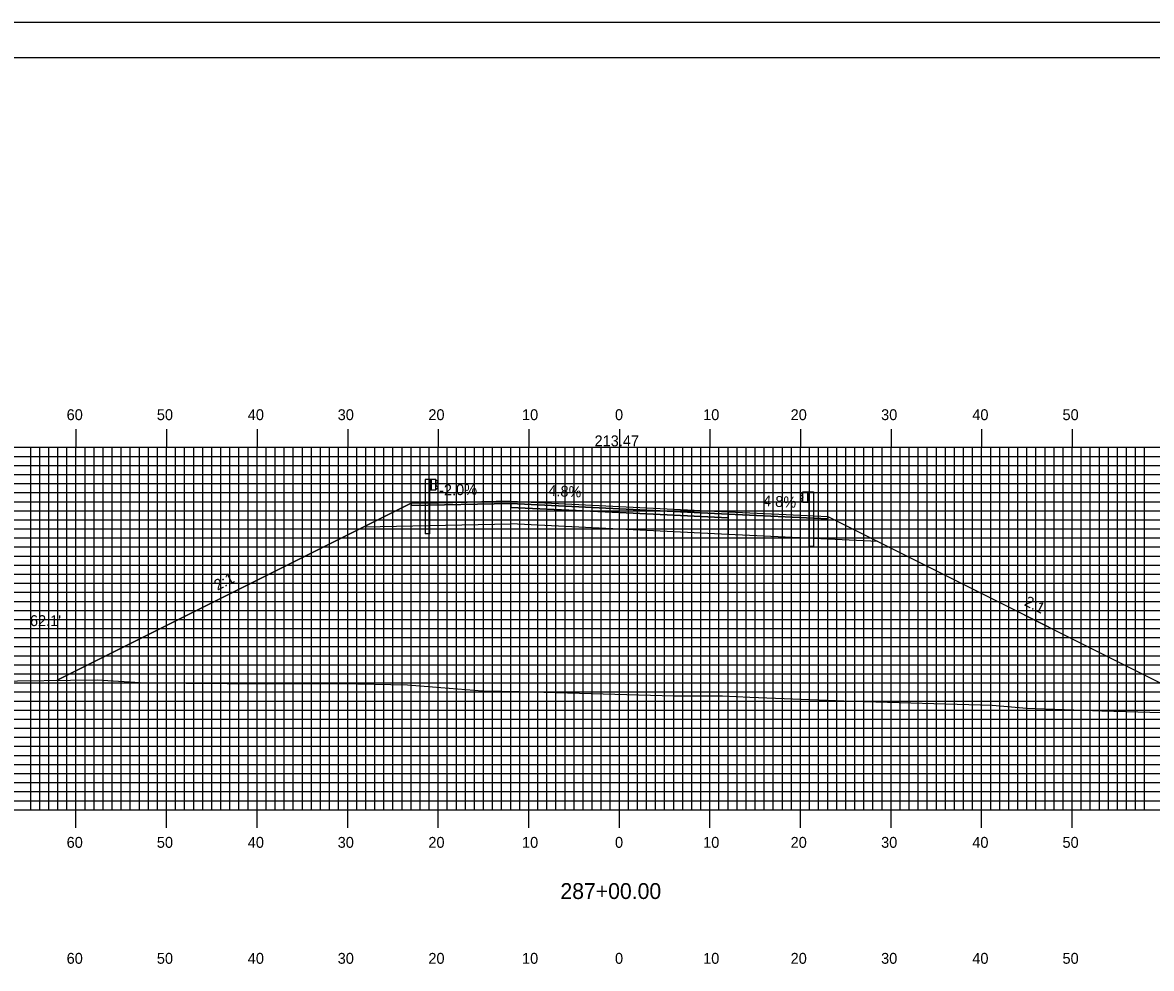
# Model space of a CAD drawing. Extents: x 1812554 to 1812897, y 442591 to 442811.
# Drawn here: x 1812654 to 1812778.7, y 442706.2 to 442810.5 of the extents above; entities that cross this region are included whole.
import ezdxf

# ---------------------------------------------------------------- set-up
doc = ezdxf.new("R2010")
doc.units = 0
for name, color, linetype in [('ANNOTATION', 7, 'Continuous'), ('BORDER', 7, 'Continuous'), ('D_Guardrail_Beam_Lt', 7, 'Continuous'), ('D_Guardrail_Beam_Rt', 7, 'Continuous'), ('D_Roadway_Centerline', 7, 'Continuous'), ('D_Roadway_Centerline_Text', 7, 'Continuous'), ('D_Roadway_Edge_Shoulder', 7, 'Continuous'), ('D_Roadway_Edge_TW', 7, 'Continuous'), ('D_Roadway_Pavement', 7, 'Continuous'), ('D_Roadway_SlopeLines', 7, 'Continuous'), ('D_Roadway_SubGrade', 7, 'Continuous'), ('D_Text_Standard', 7, 'Continuous'), ('H_V ANNOTATION', 7, 'Continuous'), ('MAJOR', 7, 'Continuous'), ('MINOR', 7, 'Continuous'), ('PLOT BOUNDARY', 7, 'Continuous'), ('S_Roadway_Centerline', 7, 'Continuous')]:
    doc.layers.add(name, color=color, linetype=linetype)

msp = doc.modelspace()

# ---------------------------------------------------------------- linework, layer by layer
at = {"layer": 'BORDER'}
msp.add_lwpolyline([(1812570.34, 442596.67), (1812890.34, 442596.67), (1812890.34, 442806.67), (1812570.34, 442806.67)], close=True, dxfattribs=at)
at = {"layer": 'D_Guardrail_Beam_Lt'}
for p, q in [((1812698.51, 442760.13), (1812698.51, 442754.13)), ((1812698.98, 442760.13), (1812698.51, 442760.13)), ((1812699.67, 442760.13), (1812698.98, 442760.13)), ((1812698.98, 442760.13), (1812698.98, 442758.96)), ((1812699.05, 442760.13), (1812699.05, 442758.96)), ((1812699.15, 442760.13), (1812699.15, 442758.96)), ((1812699.67, 442758.96), (1812699.67, 442760.13)), ((1812699.67, 442760.05), (1812699.75, 442760.03)), ((1812699.68, 442759.58), (1812699.68, 442759.51)), ((1812699.9, 442759.78), (1812699.71, 442759.65)), ((1812699.71, 442759.45), (1812699.9, 442759.31)), ((1812699.76, 442760.03), (1812699.9, 442759.93)), ((1812699.9, 442759.17), (1812699.76, 442759.07)), ((1812698.98, 442758.96), (1812699.67, 442758.96)), ((1812699, 442754.13), (1812699, 442758.96)), ((1812699.75, 442759.06), (1812699.67, 442759.05)), ((1812699, 442754.13), (1812698.51, 442754.13))]:
    msp.add_line(p, q, dxfattribs=at)
for centre, major_axis, start_param, end_param in [((1812699.75, 442759.58), (-0.0789, 0), 5.323254, 6.283185), ((1812699.75, 442759.51), (-0.0789, 0), 6.283185, 7.243116), ((1812699.74, 442759.99), (0.0417, 0), 0.959931, 1.376053), ((1812699.85, 442759.85), (0.0877, 0), 5.323254, 7.243116), ((1812699.85, 442759.24), (0.0877, 0), 5.323254, 7.243116), ((1812699.74, 442759.1), (0.0417, 0), 4.907132, 5.323254)]:
    msp.add_ellipse(centre, major_axis=major_axis, ratio=0.995501, start_param=start_param, end_param=end_param, dxfattribs=at)
at = {"layer": 'D_Guardrail_Beam_Rt'}
for p, q in [((1812740.12, 442758.65), (1812739.98, 442758.55)), ((1812739.98, 442758.41), (1812740.17, 442758.27)), ((1812740.17, 442758.07), (1812739.98, 442757.94)), ((1812740.21, 442758.67), (1812740.14, 442758.66)), ((1812740.21, 442758.75), (1812740.9, 442758.75)), ((1812740.21, 442757.59), (1812740.21, 442758.75)), ((1812740.21, 442758.21), (1812740.21, 442758.14)), ((1812740.73, 442758.75), (1812740.73, 442757.59)), ((1812740.84, 442758.75), (1812740.84, 442757.59)), ((1812740.9, 442758.75), (1812741.37, 442758.75)), ((1812740.9, 442758.75), (1812740.9, 442757.59)), ((1812741.37, 442758.75), (1812741.37, 442752.75)), ((1812739.98, 442757.79), (1812740.12, 442757.69)), ((1812740.14, 442757.69), (1812740.21, 442757.67)), ((1812740.9, 442757.59), (1812740.21, 442757.59)), ((1812740.88, 442752.75), (1812740.88, 442757.59)), ((1812740.88, 442752.75), (1812741.37, 442752.75))]:
    msp.add_line(p, q, dxfattribs=at)
for centre, major_axis, start_param, end_param in [((1812740.03, 442758.48), (-0.0877, 0), 5.323254, 7.243116), ((1812740.03, 442757.86), (-0.0877, 0), 5.323254, 7.243116), ((1812740.15, 442758.62), (-0.0417, 0), 4.907132, 5.323254), ((1812740.13, 442758.21), (0.0789, 0), 0, 0.959931), ((1812740.13, 442758.14), (0.0789, 0), 5.323254, 6.283185), ((1812740.15, 442757.73), (-0.0417, 0), 0.959931, 1.376053)]:
    msp.add_ellipse(centre, major_axis=major_axis, ratio=0.995501, start_param=start_param, end_param=end_param, dxfattribs=at)
at = {"layer": 'D_Roadway_Centerline'}
msp.add_lwpolyline([(1812657.88, 442737.96), (1812691.73, 442754.88), (1812696.94, 442757.49), (1812699.94, 442757.55), (1812707.94, 442757.71), (1812719.94, 442757.13), (1812731.94, 442756.55), (1812739.94, 442756.17), (1812742.94, 442756.03), (1812748.47, 442753.26), (1812786.29, 442734.35)], dxfattribs=at)
at = {"layer": 'D_Roadway_Edge_Shoulder'}
for points in [[(1812707.94, 442757.71), (1812699.94, 442757.55), (1812699.94, 442757.55), (1812696.94, 442757.49), (1812696.94, 442757.24), (1812707.94, 442757.46)], [(1812731.94, 442756.55), (1812739.94, 442756.17), (1812739.94, 442756.17), (1812742.94, 442756.03), (1812742.94, 442755.78), (1812731.94, 442756.3)]]:
    msp.add_lwpolyline(points, close=True, dxfattribs=at)
at = {"layer": 'D_Roadway_Edge_TW'}
msp.add_lwpolyline([(1812707.94, 442757.46), (1812707.94, 442757.71), (1812719.94, 442757.13), (1812731.94, 442756.55), (1812731.94, 442756.3), (1812719.94, 442756.88)], close=True, dxfattribs=at)
at = {"layer": 'D_Roadway_Pavement'}
msp.add_lwpolyline([(1812707.94, 442757.04), (1812707.94, 442757.46), (1812719.94, 442756.88), (1812731.94, 442756.3), (1812731.94, 442755.89), (1812719.94, 442756.46)], close=True, dxfattribs=at)
for points in [[(1812707.94, 442757.46), (1812707.94, 442757.04)], [(1812731.94, 442756.3), (1812731.94, 442755.89)]]:
    msp.add_lwpolyline(points, dxfattribs=at)
at = {"layer": 'D_Roadway_SlopeLines'}
for points in [[(1812696.94, 442757.49), (1812657.88, 442737.96)], [(1812742.94, 442756.03), (1812786.29, 442734.35)]]:
    msp.add_lwpolyline(points, dxfattribs=at)
at = {"layer": 'D_Roadway_SubGrade'}
for points in [[(1812707.94, 442757.04), (1812707.94, 442757.46), (1812696.94, 442757.24), (1812696.94, 442757.49), (1812691.73, 442754.88), (1812707.94, 442755.21)], [(1812707.94, 442755.21), (1812707.94, 442757.46), (1812707.94, 442757.04), (1812719.94, 442756.46), (1812731.94, 442755.89), (1812731.94, 442756.3), (1812731.94, 442754.05), (1812719.94, 442754.63)], [(1812731.94, 442755.89), (1812731.94, 442756.3), (1812742.94, 442755.78), (1812742.94, 442756.03), (1812748.47, 442753.26), (1812731.94, 442754.05)]]:
    msp.add_lwpolyline(points, close=True, dxfattribs=at)
at = {"layer": 'MAJOR'}
for p, q in [((1812659.94, 442765.67), (1812659.94, 442763.67)), ((1812669.94, 442765.67), (1812669.94, 442763.67)), ((1812679.94, 442765.67), (1812679.94, 442763.67)), ((1812689.94, 442765.67), (1812689.94, 442763.67)), ((1812699.94, 442765.67), (1812699.94, 442763.67)), ((1812709.94, 442765.67), (1812709.94, 442763.67)), ((1812719.94, 442765.67), (1812719.94, 442763.67)), ((1812729.94, 442765.67), (1812729.94, 442763.67)), ((1812739.94, 442765.67), (1812739.94, 442763.67)), ((1812749.94, 442765.67), (1812749.94, 442763.67)), ((1812759.94, 442765.67), (1812759.94, 442763.67)), ((1812769.94, 442765.67), (1812769.94, 442763.67)), ((1812579.94, 442763.67), (1812859.94, 442763.67)), ((1812579.94, 442763.67), (1812859.94, 442763.67)), ((1812659.94, 442723.67), (1812659.94, 442763.67)), ((1812669.94, 442723.67), (1812669.94, 442763.67)), ((1812679.94, 442723.67), (1812679.94, 442763.67)), ((1812689.94, 442723.67), (1812689.94, 442763.67)), ((1812699.94, 442723.67), (1812699.94, 442763.67)), ((1812709.94, 442723.67), (1812709.94, 442763.67)), ((1812719.94, 442723.67), (1812719.94, 442763.67)), ((1812729.94, 442723.67), (1812729.94, 442763.67)), ((1812739.94, 442723.67), (1812739.94, 442763.67)), ((1812749.94, 442723.67), (1812749.94, 442763.67)), ((1812759.94, 442723.67), (1812759.94, 442763.67)), ((1812769.94, 442723.67), (1812769.94, 442763.67)), ((1812579.94, 442758.67), (1812859.94, 442758.67)), ((1812579.94, 442753.67), (1812859.94, 442753.67)), ((1812579.94, 442748.67), (1812859.94, 442748.67)), ((1812579.94, 442743.67), (1812859.94, 442743.67)), ((1812579.94, 442738.67), (1812859.94, 442738.67)), ((1812579.94, 442733.67), (1812859.94, 442733.67)), ((1812579.94, 442728.67), (1812859.94, 442728.67)), ((1812579.94, 442723.67), (1812859.94, 442723.67)), ((1812579.94, 442723.67), (1812859.94, 442723.67)), ((1812659.94, 442721.66), (1812659.94, 442723.67)), ((1812669.94, 442721.66), (1812669.94, 442723.67)), ((1812679.94, 442721.66), (1812679.94, 442723.67)), ((1812689.94, 442721.66), (1812689.94, 442723.67)), ((1812699.94, 442721.66), (1812699.94, 442723.67)), ((1812709.94, 442721.66), (1812709.94, 442723.67)), ((1812719.94, 442721.66), (1812719.94, 442723.67)), ((1812729.94, 442721.66), (1812729.94, 442723.67)), ((1812739.94, 442721.66), (1812739.94, 442723.67)), ((1812749.94, 442721.66), (1812749.94, 442723.67)), ((1812759.94, 442721.66), (1812759.94, 442723.67)), ((1812769.94, 442721.66), (1812769.94, 442723.67))]:
    msp.add_line(p, q, dxfattribs=at)
at = {"layer": 'MINOR'}
for p, q in [((1812654.94, 442723.67), (1812654.94, 442763.67)), ((1812655.94, 442723.67), (1812655.94, 442763.67)), ((1812656.94, 442723.67), (1812656.94, 442763.67)), ((1812657.94, 442723.67), (1812657.94, 442763.67)), ((1812658.94, 442723.67), (1812658.94, 442763.67)), ((1812660.94, 442723.67), (1812660.94, 442763.67)), ((1812661.94, 442723.67), (1812661.94, 442763.67)), ((1812662.94, 442723.67), (1812662.94, 442763.67)), ((1812663.94, 442723.67), (1812663.94, 442763.67)), ((1812664.94, 442723.67), (1812664.94, 442763.67)), ((1812665.94, 442723.67), (1812665.94, 442763.67)), ((1812666.94, 442723.67), (1812666.94, 442763.67)), ((1812667.94, 442723.67), (1812667.94, 442763.67)), ((1812668.94, 442723.67), (1812668.94, 442763.67)), ((1812670.94, 442723.67), (1812670.94, 442763.67)), ((1812671.94, 442723.67), (1812671.94, 442763.67)), ((1812672.94, 442723.67), (1812672.94, 442763.67)), ((1812673.94, 442723.67), (1812673.94, 442763.67)), ((1812674.94, 442723.67), (1812674.94, 442763.67)), ((1812675.94, 442723.67), (1812675.94, 442763.67)), ((1812676.94, 442723.67), (1812676.94, 442763.67)), ((1812677.94, 442723.67), (1812677.94, 442763.67)), ((1812678.94, 442723.67), (1812678.94, 442763.67)), ((1812680.94, 442723.67), (1812680.94, 442763.67)), ((1812681.94, 442723.67), (1812681.94, 442763.67)), ((1812682.94, 442723.67), (1812682.94, 442763.67)), ((1812683.94, 442723.67), (1812683.94, 442763.67)), ((1812684.94, 442723.67), (1812684.94, 442763.67)), ((1812685.94, 442723.67), (1812685.94, 442763.67)), ((1812686.94, 442723.67), (1812686.94, 442763.67)), ((1812687.94, 442723.67), (1812687.94, 442763.67)), ((1812688.94, 442723.67), (1812688.94, 442763.67)), ((1812690.94, 442723.67), (1812690.94, 442763.67)), ((1812691.94, 442723.67), (1812691.94, 442763.67)), ((1812692.94, 442723.67), (1812692.94, 442763.67)), ((1812693.94, 442723.67), (1812693.94, 442763.67)), ((1812694.94, 442723.67), (1812694.94, 442763.67)), ((1812695.94, 442723.67), (1812695.94, 442763.67)), ((1812696.94, 442723.67), (1812696.94, 442763.67)), ((1812697.94, 442723.67), (1812697.94, 442763.67)), ((1812698.94, 442723.67), (1812698.94, 442763.67)), ((1812700.94, 442723.67), (1812700.94, 442763.67)), ((1812701.94, 442723.67), (1812701.94, 442763.67)), ((1812702.94, 442723.67), (1812702.94, 442763.67)), ((1812703.94, 442723.67), (1812703.94, 442763.67)), ((1812704.94, 442723.67), (1812704.94, 442763.67)), ((1812705.94, 442723.67), (1812705.94, 442763.67)), ((1812706.94, 442723.67), (1812706.94, 442763.67)), ((1812707.94, 442723.67), (1812707.94, 442763.67)), ((1812708.94, 442723.67), (1812708.94, 442763.67)), ((1812710.94, 442723.67), (1812710.94, 442763.67)), ((1812711.94, 442723.67), (1812711.94, 442763.67)), ((1812712.94, 442723.67), (1812712.94, 442763.67)), ((1812713.94, 442723.67), (1812713.94, 442763.67)), ((1812714.94, 442723.67), (1812714.94, 442763.67)), ((1812715.94, 442723.67), (1812715.94, 442763.67)), ((1812716.94, 442723.67), (1812716.94, 442763.67)), ((1812717.94, 442723.67), (1812717.94, 442763.67)), ((1812718.94, 442723.67), (1812718.94, 442763.67)), ((1812720.94, 442723.67), (1812720.94, 442763.67)), ((1812721.94, 442723.67), (1812721.94, 442763.67)), ((1812722.94, 442723.67), (1812722.94, 442763.67)), ((1812723.94, 442723.67), (1812723.94, 442763.67)), ((1812724.94, 442723.67), (1812724.94, 442763.67)), ((1812725.94, 442723.67), (1812725.94, 442763.67)), ((1812726.94, 442723.67), (1812726.94, 442763.67)), ((1812727.94, 442723.67), (1812727.94, 442763.67)), ((1812728.94, 442723.67), (1812728.94, 442763.67)), ((1812730.94, 442723.67), (1812730.94, 442763.67)), ((1812731.94, 442723.67), (1812731.94, 442763.67)), ((1812732.94, 442723.67), (1812732.94, 442763.67)), ((1812733.94, 442723.67), (1812733.94, 442763.67)), ((1812734.94, 442723.67), (1812734.94, 442763.67)), ((1812735.94, 442723.67), (1812735.94, 442763.67)), ((1812736.94, 442723.67), (1812736.94, 442763.67)), ((1812737.94, 442723.67), (1812737.94, 442763.67)), ((1812738.94, 442723.67), (1812738.94, 442763.67)), ((1812740.94, 442723.67), (1812740.94, 442763.67)), ((1812741.94, 442723.67), (1812741.94, 442763.67)), ((1812742.94, 442723.67), (1812742.94, 442763.67)), ((1812743.94, 442723.67), (1812743.94, 442763.67)), ((1812744.94, 442723.67), (1812744.94, 442763.67)), ((1812745.94, 442723.67), (1812745.94, 442763.67)), ((1812746.94, 442723.67), (1812746.94, 442763.67)), ((1812747.94, 442723.67), (1812747.94, 442763.67)), ((1812748.94, 442723.67), (1812748.94, 442763.67)), ((1812750.94, 442723.67), (1812750.94, 442763.67)), ((1812751.94, 442723.67), (1812751.94, 442763.67)), ((1812752.94, 442723.67), (1812752.94, 442763.67)), ((1812753.94, 442723.67), (1812753.94, 442763.67)), ((1812754.94, 442723.67), (1812754.94, 442763.67)), ((1812755.94, 442723.67), (1812755.94, 442763.67)), ((1812756.94, 442723.67), (1812756.94, 442763.67)), ((1812757.94, 442723.67), (1812757.94, 442763.67)), ((1812758.94, 442723.67), (1812758.94, 442763.67)), ((1812760.94, 442723.67), (1812760.94, 442763.67)), ((1812761.94, 442723.67), (1812761.94, 442763.67)), ((1812762.94, 442723.67), (1812762.94, 442763.67)), ((1812763.94, 442723.67), (1812763.94, 442763.67)), ((1812764.94, 442723.67), (1812764.94, 442763.67)), ((1812765.94, 442723.67), (1812765.94, 442763.67)), ((1812766.94, 442723.67), (1812766.94, 442763.67)), ((1812767.94, 442723.67), (1812767.94, 442763.67)), ((1812768.94, 442723.67), (1812768.94, 442763.67)), ((1812770.94, 442723.67), (1812770.94, 442763.67)), ((1812771.94, 442723.67), (1812771.94, 442763.67)), ((1812772.94, 442723.67), (1812772.94, 442763.67)), ((1812773.94, 442723.67), (1812773.94, 442763.67)), ((1812774.94, 442723.67), (1812774.94, 442763.67)), ((1812775.94, 442723.67), (1812775.94, 442763.67)), ((1812776.94, 442723.67), (1812776.94, 442763.67)), ((1812777.94, 442723.67), (1812777.94, 442763.67)), ((1812579.94, 442762.67), (1812859.94, 442762.67)), ((1812579.94, 442761.67), (1812859.94, 442761.67)), ((1812579.94, 442760.67), (1812859.94, 442760.67)), ((1812579.94, 442759.67), (1812859.94, 442759.67)), ((1812579.94, 442757.67), (1812859.94, 442757.67)), ((1812579.94, 442756.67), (1812859.94, 442756.67)), ((1812579.94, 442755.67), (1812859.94, 442755.67)), ((1812579.94, 442754.67), (1812859.94, 442754.67)), ((1812579.94, 442752.67), (1812859.94, 442752.67)), ((1812579.94, 442751.67), (1812859.94, 442751.67)), ((1812579.94, 442750.67), (1812859.94, 442750.67)), ((1812579.94, 442749.67), (1812859.94, 442749.67)), ((1812579.94, 442747.67), (1812859.94, 442747.67)), ((1812579.94, 442746.67), (1812859.94, 442746.67)), ((1812579.94, 442745.67), (1812859.94, 442745.67)), ((1812579.94, 442744.67), (1812859.94, 442744.67)), ((1812579.94, 442742.67), (1812859.94, 442742.67)), ((1812579.94, 442741.67), (1812859.94, 442741.67)), ((1812579.94, 442740.67), (1812859.94, 442740.67)), ((1812579.94, 442739.67), (1812859.94, 442739.67)), ((1812579.94, 442737.67), (1812859.94, 442737.67)), ((1812579.94, 442736.67), (1812859.94, 442736.67)), ((1812579.94, 442735.67), (1812859.94, 442735.67)), ((1812579.94, 442734.67), (1812859.94, 442734.67)), ((1812579.94, 442732.67), (1812859.94, 442732.67)), ((1812579.94, 442731.67), (1812859.94, 442731.67)), ((1812579.94, 442730.67), (1812859.94, 442730.67)), ((1812579.94, 442729.67), (1812859.94, 442729.67)), ((1812579.94, 442727.67), (1812859.94, 442727.67)), ((1812579.94, 442726.67), (1812859.94, 442726.67)), ((1812579.94, 442725.67), (1812859.94, 442725.67)), ((1812579.94, 442724.67), (1812859.94, 442724.67))]:
    msp.add_line(p, q, dxfattribs=at)
at = {"layer": 'PLOT BOUNDARY'}
msp.add_lwpolyline([(1812554.16, 442590.55), (1812894.16, 442590.55), (1812894.16, 442810.55), (1812554.16, 442810.55)], close=True, dxfattribs=at)
at = {"layer": 'S_Roadway_Centerline'}
msp.add_lwpolyline([(1812650.51, 442737.86), (1812662.27, 442738.01), (1812667.63, 442737.69), (1812681.11, 442737.57), (1812689.22, 442737.59), (1812696.55, 442737.46), (1812704.84, 442736.81), (1812708.98, 442736.71), (1812725.99, 442736.26), (1812731.33, 442736.25), (1812734.35, 442736.11), (1812745.68, 442735.65), (1812761.12, 442735.23), (1812764.93, 442734.89), (1812773.23, 442734.57), (1812782.47, 442734.32)], dxfattribs=at)

# ---------------------------------------------------------------- texts
at = {"layer": 'ANNOTATION'}
for s, rotation, p in [('-2.0%', 1.1458, (1812700.05, 442758.35)), ('4.8%', 357.2519, (1812712.07, 442758.31)), ('-4.8%', 357.2519, (1812735.25, 442757.2)), ('2:1', 26.5651, (1812675.56, 442747.83)), ('2:1', 333.4349, (1812764.55, 442746.26))]:
    msp.add_text(s, height=1.2, rotation=rotation, dxfattribs=at).set_placement(p)
at = {"layer": 'D_Roadway_Centerline'}
for s, p in [('C', (1812719.94, 442757.13)), ('L', (1812719.94, 442757.12))]:
    msp.add_text(s, height=0.0146, dxfattribs=at).set_placement(p)
at = {"layer": 'D_Roadway_Centerline_Text'}
msp.add_text('213.47', height=1.2, dxfattribs=at).set_placement((1812717.2, 442763.78))
at = {"layer": 'D_Text_Standard'}
msp.add_text("62.1'", height=1.2, dxfattribs=at).set_placement((1812654.86, 442743.94))
at = {"layer": 'H_V ANNOTATION'}
for s, height, p in [('60', 1.2, (1812658.91, 442766.67)), ('50', 1.2, (1812668.87, 442766.67)), ('40', 1.2, (1812678.91, 442766.67)), ('30', 1.2, (1812688.84, 442766.67)), ('20', 1.2, (1812698.85, 442766.67)), ('10', 1.2, (1812709.19, 442766.67)), ('0', 1.2, (1812719.46, 442766.67)), ('10', 1.2, (1812729.19, 442766.67)), ('20', 1.2, (1812738.85, 442766.67)), ('30', 1.2, (1812748.84, 442766.67)), ('40', 1.2, (1812758.91, 442766.67)), ('50', 1.2, (1812768.87, 442766.67)), ('60', 1.2, (1812658.91, 442719.47)), ('50', 1.2, (1812668.87, 442719.47)), ('40', 1.2, (1812678.91, 442719.47)), ('30', 1.2, (1812688.84, 442719.47)), ('20', 1.2, (1812698.85, 442719.47)), ('10', 1.2, (1812709.19, 442719.47)), ('0', 1.2, (1812719.46, 442719.47)), ('10', 1.2, (1812729.19, 442719.47)), ('20', 1.2, (1812738.85, 442719.47)), ('30', 1.2, (1812748.84, 442719.47)), ('40', 1.2, (1812758.91, 442719.47)), ('50', 1.2, (1812768.87, 442719.47)), ('287+00.00', 1.75, (1812713.43, 442713.82)), ('60', 1.2, (1812658.91, 442706.67)), ('50', 1.2, (1812668.87, 442706.67)), ('40', 1.2, (1812678.91, 442706.67)), ('30', 1.2, (1812688.84, 442706.67)), ('20', 1.2, (1812698.85, 442706.67)), ('10', 1.2, (1812709.19, 442706.67)), ('0', 1.2, (1812719.46, 442706.67)), ('10', 1.2, (1812729.19, 442706.67)), ('20', 1.2, (1812738.85, 442706.67)), ('30', 1.2, (1812748.84, 442706.67)), ('40', 1.2, (1812758.91, 442706.67)), ('50', 1.2, (1812768.87, 442706.67))]:
    msp.add_text(s, height=height, dxfattribs=at).set_placement(p)

doc.saveas('drawing.dxf')
